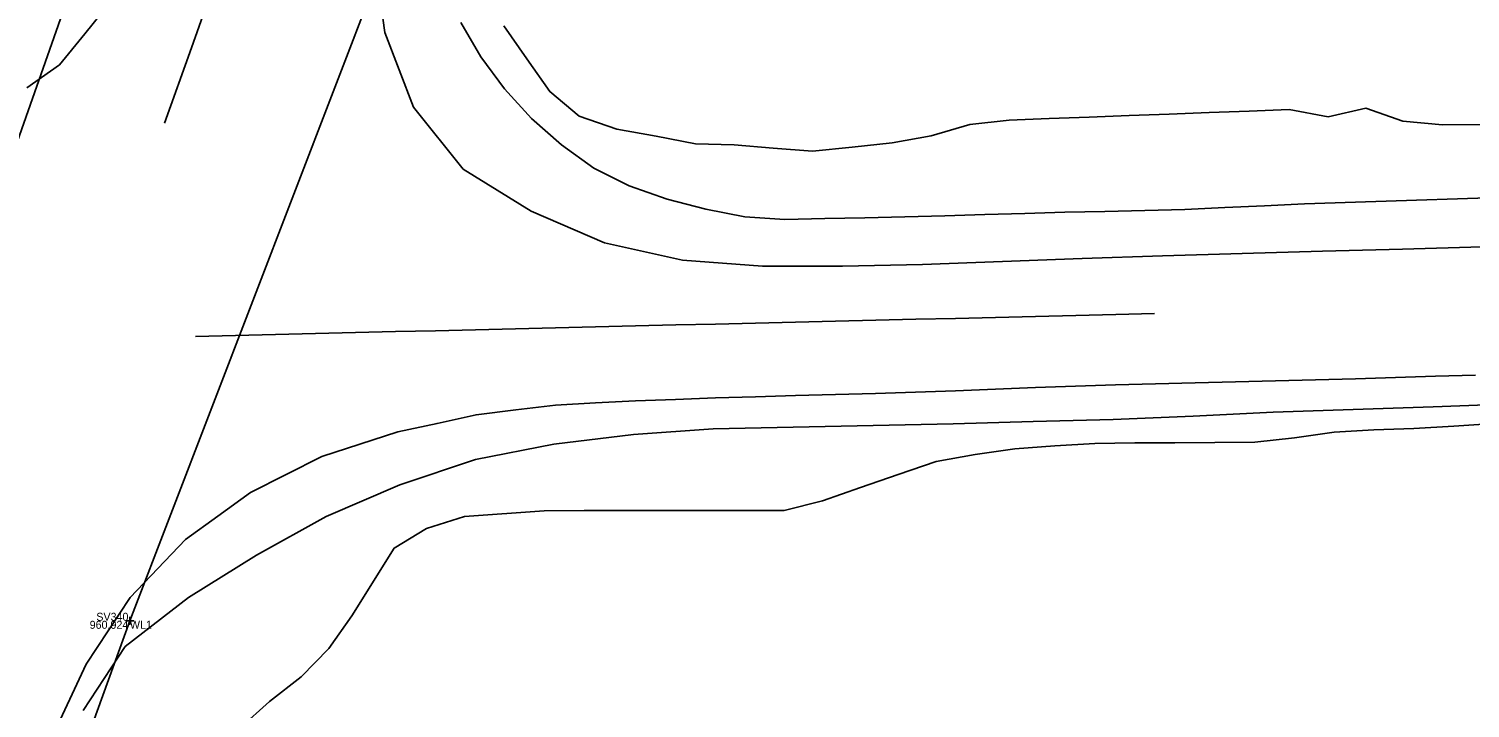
# Model space of a CAD drawing. Extents: x 2262025 to 2264532, y 740981 to 742724.
# Drawn here: x 2263322.3 to 2263502.4, y 742345.3 to 742430.2 of the extents above; entities that cross this region are included whole.
import ezdxf

# ---------------------------------------------------------------- set-up
doc = ezdxf.new("R2010")
doc.units = 0
for name, color, linetype in [('DT_X_Break_Line', 7, 'Continuous'), ('GE_X_Alignment_100_Curve_Data', 7, 'Continuous'), ('HY_X_Spring_Cells', 7, 'Continuous'), ('RW_X_CL', 7, 'Continuous'), ('RW_X_CL_1000_Distances', 7, 'Continuous'), ('RW_X_CL_100_Cardinal_Points', 7, 'Continuous'), ('SC_Scratch4', 7, 'Continuous'), ('SV_X_Control_Cells_Found', 7, 'Continuous'), ('SV_X_Text_Comment', 7, 'Continuous'), ('UT_X_Gas', 7, 'Continuous'), ('UT_X_Water', 7, 'Continuous')]:
    doc.layers.add(name, color=color, linetype=linetype)

msp = doc.modelspace()

# ---------------------------------------------------------------- linework, layer by layer
at = {"layer": 'DT_X_Break_Line'}
msp.add_lwpolyline([(2263343.15, 742391.76), (2263348.15, 742391.88), (2263353.15, 742391.99), (2263358.15, 742392.11), (2263363.15, 742392.23), (2263368.15, 742392.35), (2263373.14, 742392.47), (2263378.14, 742392.59), (2263383.14, 742392.7), (2263388.14, 742392.82), (2263393.14, 742392.94), (2263398.14, 742393.06), (2263403.14, 742393.18), (2263408.13, 742393.3), (2263413.13, 742393.42), (2263418.13, 742393.53), (2263423.13, 742393.65), (2263428.13, 742393.77), (2263433.13, 742393.89), (2263438.12, 742394.01), (2263443.12, 742394.13), (2263448.12, 742394.24), (2263453.12, 742394.36), (2263458.12, 742394.48), (2263462.98, 742394.6)], dxfattribs=at)
at = {"layer": 'GE_X_Alignment_100_Curve_Data'}
for points in [[(2263514.81, 742409.4), (2263481.73, 742408.32), (2263476.73, 742408.08), (2263471.74, 742407.85), (2263466.74, 742407.63), (2263461.75, 742407.47), (2263456.75, 742407.38), (2263451.75, 742407.26), (2263446.75, 742407.11), (2263441.75, 742406.97), (2263436.76, 742406.83), (2263431.76, 742406.7), (2263426.76, 742406.58), (2263421.76, 742406.47), (2263416.76, 742406.36), (2263411.8, 742406.71), (2263406.89, 742407.64), (2263402.07, 742408.9), (2263397.35, 742410.56), (2263392.93, 742412.79), (2263388.86, 742415.7), (2263385.12, 742418.97), (2263381.76, 742422.68), (2263378.8, 742426.67), (2263376.28, 742430.99)], [(2263507.77, 742383.31), (2263497.77, 742382.95), (2263487.78, 742382.6), (2263477.78, 742382.29), (2263467.8, 742381.79), (2263457.81, 742381.39), (2263447.81, 742381.1), (2263437.81, 742380.81), (2263427.82, 742380.6), (2263417.82, 742380.4), (2263407.82, 742380.19), (2263397.86, 742379.48), (2263387.93, 742378.27), (2263378.14, 742376.36), (2263368.66, 742373.19), (2263359.47, 742369.27), (2263350.75, 742364.4), (2263342.25, 742359.13), (2263334.36, 742353), (2263329.09, 742345)]]:
    msp.add_lwpolyline(points, dxfattribs=at)
at = {"layer": 'RW_X_CL_1000_Distances'}
for points in [[(2263503.93, 742402.93), (2263493.94, 742402.67), (2263483.94, 742402.42), (2263473.94, 742402.12), (2263463.95, 742401.82), (2263453.95, 742401.5), (2263443.96, 742401.12), (2263433.97, 742400.75), (2263423.97, 742400.54), (2263413.97, 742400.54), (2263404.01, 742401.3), (2263394.25, 742403.44), (2263385.08, 742407.4), (2263376.6, 742412.67), (2263370.4, 742420.41), (2263366.8, 742429.72), (2263365.41, 742439.61)], [(2263322.06, 742422.8), (2263326.15, 742425.68), (2263329.31, 742429.55), (2263332.46, 742433.43)], [(2263329.49, 742350.79), (2263332.25, 742354.96), (2263335, 742359.13), (2263338.44, 742362.76), (2263341.89, 742366.38), (2263345.94, 742369.31), (2263350, 742372.23), (2263354.46, 742374.5), (2263358.92, 742376.75), (2263363.68, 742378.28), (2263368.44, 742379.81), (2263373.32, 742380.89), (2263378.21, 742381.96), (2263383.17, 742382.57), (2263388.13, 742383.18), (2263393.12, 742383.45), (2263398.12, 742383.72), (2263403.11, 742383.89), (2263408.11, 742384.06), (2263413.11, 742384.2), (2263418.11, 742384.35), (2263423.1, 742384.49), (2263428.1, 742384.63), (2263433.1, 742384.8), (2263438.09, 742384.96), (2263443.09, 742385.15), (2263448.09, 742385.35), (2263453.08, 742385.52), (2263458.08, 742385.7), (2263463.08, 742385.83), (2263468.07, 742385.97), (2263473.07, 742386.08), (2263478.07, 742386.19), (2263483.07, 742386.32), (2263488.07, 742386.44), (2263493.06, 742386.61), (2263498.06, 742386.77), (2263503.08, 742386.93)], [(2263325.59, 742342.51), (2263327.72, 742347.03), (2263329.49, 742350.79)]]:
    msp.add_lwpolyline(points, dxfattribs=at)
at = {"layer": 'RW_X_CL_100_Cardinal_Points'}
for p, q in [((2263334.45, 742356.22), (2263335.45, 742356.22)), ((2263334.95, 742356.72), (2263334.95, 742355.72)), ((2263334.95, 742356.22), (2263334.95, 742356.22))]:
    msp.add_line(p, q, dxfattribs=at)
at = {"layer": 'SC_Scratch4'}
msp.add_lwpolyline([(2263339.28, 742418.41), (2263342.63, 742427.83), (2263345.98, 742437.26), (2263349.34, 742446.68), (2263352.69, 742456.1), (2263356.04, 742465.52), (2263359.38, 742474.95), (2263362.72, 742484.37), (2263366.07, 742493.79), (2263369.41, 742503.22), (2263372.77, 742512.64), (2263376.13, 742522.05), (2263379.5, 742531.47), (2263382.86, 742540.89), (2263386.23, 742550.3), (2263389.6, 742559.72), (2263391.48, 742564.96)], dxfattribs=at)
at = {"layer": 'SV_X_Control_Cells_Found'}
for points in [[(2263503.92, 742418.25), (2263498.96, 742418.2), (2263493.98, 742418.65), (2263489.38, 742420.26), (2263484.67, 742419.2), (2263479.79, 742420.09), (2263474.79, 742419.91), (2263469.8, 742419.72), (2263464.8, 742419.53), (2263459.8, 742419.34), (2263454.81, 742419.16), (2263449.81, 742418.97), (2263444.81, 742418.78), (2263439.88, 742418.22), (2263435.08, 742416.81), (2263430.18, 742415.95), (2263425.2, 742415.42), (2263420.23, 742414.88), (2263415.31, 742415.29), (2263410.46, 742415.68), (2263405.62, 742415.81), (2263400.71, 742416.76), (2263395.79, 742417.63), (2263391.09, 742419.27), (2263387.41, 742422.35), (2263384.54, 742426.44), (2263381.67, 742430.54)], [(2263505.36, 742380.89), (2263500.38, 742380.55), (2263495.39, 742380.24), (2263490.39, 742380.07), (2263485.4, 742379.8), (2263480.45, 742379.1), (2263475.5, 742378.54), (2263470.5, 742378.49), (2263465.5, 742378.45), (2263460.5, 742378.45), (2263455.5, 742378.39), (2263450.51, 742378.09), (2263445.53, 742377.7), (2263440.58, 742377), (2263435.67, 742376.11), (2263430.94, 742374.49), (2263426.22, 742372.87), (2263421.5, 742371.22), (2263416.7, 742370), (2263411.7, 742370), (2263406.71, 742370), (2263401.71, 742370), (2263396.71, 742370), (2263391.71, 742370), (2263386.71, 742369.96), (2263376.77, 742369.26), (2263372.01, 742367.74), (2263367.97, 742365.31), (2263362.69, 742356.83), (2263359.79, 742352.76), (2263356.34, 742349.21), (2263352.41, 742346.12), (2263348.68, 742342.8)]]:
    msp.add_lwpolyline(points, dxfattribs=at)
at = {"layer": 'UT_X_Gas'}
msp.add_lwpolyline([(2263370.65, 742558.56), (2263358.32, 742523.53), (2263332.75, 742449.83), (2263131.85, 741878.34), (2263108.26, 741811.62)], dxfattribs=at)
at = {"layer": 'UT_X_Water'}
msp.add_lwpolyline([(2263058.18, 741572.97), (2263085.82, 741651.25), (2263095.93, 741679.99), (2263097.95, 741685.82), (2263106.82, 741712.78), (2263147.36, 741828.66), (2263178.07, 741920.18), (2263217.98, 742032.49), (2263252.6, 742127.99), (2263295.63, 742247.6), (2263334.95, 742356.22), (2263370.78, 742449.55), (2263413.67, 742573.04), (2263421.38, 742593.43)], dxfattribs=at)

# ---------------------------------------------------------------- texts
at = {"layer": 'HY_X_Spring_Cells'}
msp.add_text('960.924', height=1, dxfattribs=at).set_placement((2263329.92, 742355.22))
at = {"layer": 'RW_X_CL'}
msp.add_text('WL1', height=1, dxfattribs=at).set_placement((2263334.95, 742355.22))
at = {"layer": 'SV_X_Text_Comment'}
msp.add_text('SV340', height=1, dxfattribs=at).set_placement((2263330.75, 742356.22))

doc.saveas('drawing.dxf')
